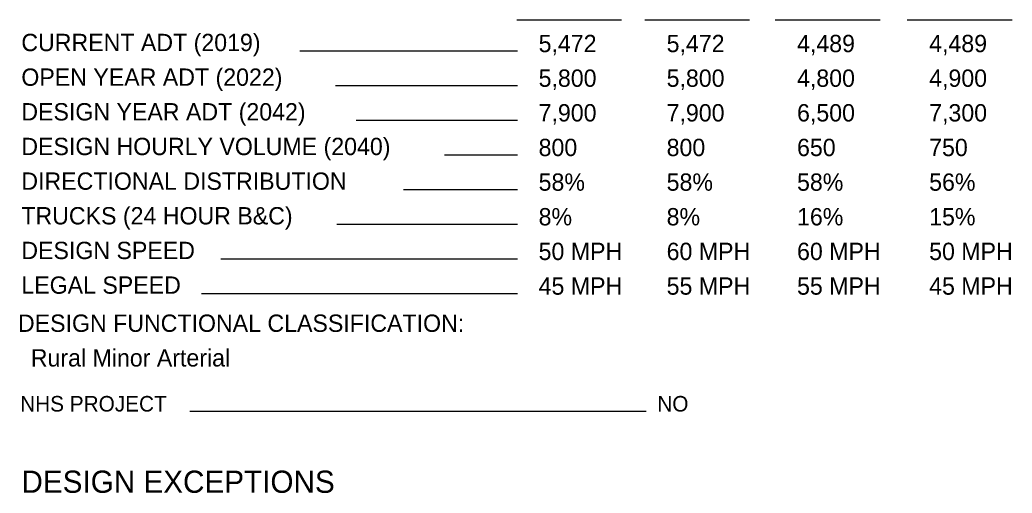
# Model space of a CAD drawing. Extents: x -17.5 to 72.9, y -57.8 to 32.3.
# Drawn here: x 41.62 to 50.56, y -51.96 to -47.7 of the extents above; entities that cross this region are included whole.
import ezdxf

# ---------------------------------------------------------------- set-up
doc = ezdxf.new("R2010")
doc.units = 0
doc.layers.add('SH_Data', color=7, linetype='Continuous')
doc.layers.add('SH_Text', color=7, linetype='Continuous')

msp = doc.modelspace()

# ---------------------------------------------------------------- linework, layer by layer
at = {"layer": 'SH_Data'}
for p, q in [((46.1004, -47.9781), (44.1401, -47.9781)), ((46.1004, -48.2901), (44.4599, -48.2901)), ((46.1004, -48.6021), (44.6488, -48.6021)), ((46.1004, -48.9141), (45.4444, -48.9141)), ((46.1004, -49.2261), (45.0727, -49.2261)), ((46.1004, -49.5381), (44.4727, -49.5381)), ((46.1004, -49.8501), (43.4292, -49.8501)), ((46.1004, -50.1621), (43.2532, -50.1621)), ((47.2615, -51.2227), (43.149, -51.2227))]:
    msp.add_line(p, q, dxfattribs=at)
at = {"layer": 'SH_Text'}
for p, q in [((46.0948, -47.6964), (47.04, -47.6964)), ((47.2486, -47.6964), (48.1938, -47.6964)), ((48.4239, -47.6964), (49.3691, -47.6964)), ((49.6145, -47.6964), (50.5598, -47.6964))]:
    msp.add_line(p, q, dxfattribs=at)

# ---------------------------------------------------------------- texts
at = {"layer": 'SH_Data'}
for s, height, p in [('CURRENT ADT (2019)', 0.156, (41.6297, -47.9781)), ('5,472', 0.15597, (46.2919, -47.9872)), ('5,472', 0.15597, (47.4457, -47.9872)), ('4,489', 0.15597, (48.621, -47.9872)), ('4,489', 0.15597, (49.8117, -47.9872)), ('OPEN YEAR ADT (2022)', 0.156, (41.6297, -48.2901)), ('5,800', 0.15597, (46.2919, -48.2992)), ('5,800', 0.15597, (47.4457, -48.2992)), ('4,800', 0.15597, (48.621, -48.2992)), ('4,900', 0.15597, (49.8117, -48.2992)), ('DESIGN YEAR ADT (2042)', 0.156, (41.6297, -48.6021)), ('7,900', 0.15597, (46.2919, -48.6111)), ('7,900', 0.15597, (47.4457, -48.6111)), ('6,500', 0.15597, (48.621, -48.6111)), ('7,300', 0.15597, (49.8117, -48.6111)), ('DESIGN HOURLY VOLUME (2040)', 0.156, (41.6297, -48.9141)), ('800', 0.15597, (46.2919, -48.923)), ('800', 0.15597, (47.4457, -48.923)), ('650', 0.15597, (48.621, -48.923)), ('750', 0.15597, (49.8117, -48.923)), ('DIRECTIONAL DISTRIBUTION', 0.155966, (41.6297, -49.2261)), ('58%', 0.15597, (46.2919, -49.235)), ('58%', 0.15597, (47.4457, -49.235)), ('58%', 0.15597, (48.621, -49.235)), ('56%', 0.15597, (49.8117, -49.235)), ('TRUCKS (24 HOUR B&C)', 0.155966, (41.6297, -49.5381)), ('8%', 0.15597, (46.2919, -49.5469)), ('8%', 0.15597, (47.4457, -49.5469)), ('16%', 0.15597, (48.621, -49.5469)), ('15%', 0.15597, (49.8117, -49.5469)), ('DESIGN SPEED', 0.155966, (41.6297, -49.8502)), ('50 MPH', 0.15597, (46.2919, -49.8588)), ('60 MPH', 0.15597, (47.4457, -49.8588)), ('60 MPH', 0.15597, (48.621, -49.8588)), ('50 MPH', 0.15597, (49.8117, -49.8588)), ('LEGAL SPEED', 0.155966, (41.6297, -50.1622)), ('45 MPH', 0.15597, (46.2919, -50.1708)), ('55 MPH', 0.15597, (47.4457, -50.1708)), ('55 MPH', 0.15597, (48.621, -50.1708)), ('45 MPH', 0.15597, (49.8117, -50.1708)), ('DESIGN FUNCTIONAL CLASSIFICATION:', 0.156, (41.5992, -50.5054)), ('  Rural Minor Arterial', 0.155966, (41.5992, -50.8174))]:
    msp.add_text(s, height=height, dxfattribs=at).set_placement(p)
at = {"layer": 'SH_Text'}
for s, height, p in [('NHS PROJECT', 0.14, (41.6191, -51.2227)), ('NO    ', 0.14, (47.3615, -51.2227)), ('DESIGN EXCEPTIONS', 0.2, (41.6306, -51.9546))]:
    msp.add_text(s, height=height, dxfattribs=at).set_placement(p)

doc.saveas('drawing.dxf')
